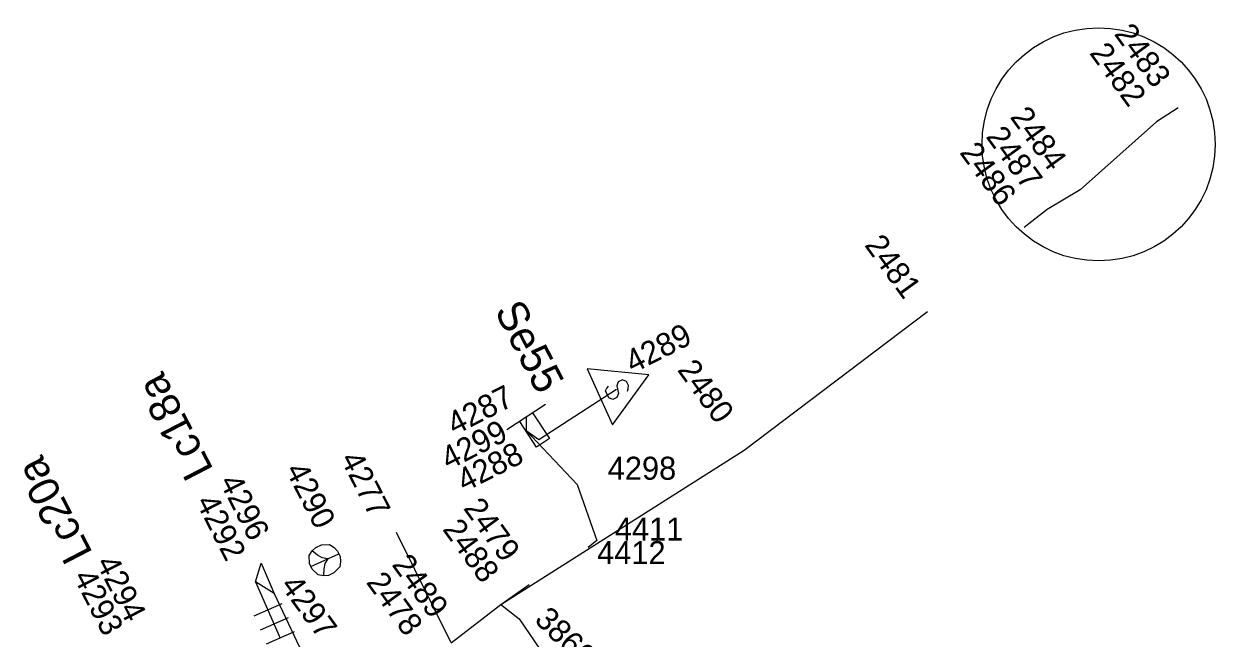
# Model space of a CAD drawing. Extents: x -535557 to -534097, y -1142175 to -1136716.
# Drawn here: x -534895.11 to -534856.28, y -1139139.7 to -1139119.68 of the extents above; entities that cross this region are included whole.
import ezdxf

# ---------------------------------------------------------------- set-up
doc = ezdxf.new("R2010")
doc.units = 0
doc.layers.add('Default', color=7, linetype='Continuous')
doc.layers.add('SS_SZDC', color=7, linetype='Continuous')

# ---------------------------------------------------------------- blocks, each defined once
blk = doc.blocks.new('POINT_DISPLAY')
at = {"layer": 'Default'}
blk.add_line((0, 0), (0, 0), dxfattribs=at)

msp = doc.modelspace()

# ---------------------------------------------------------------- linework, layer by layer
at = {"layer": 'SS_SZDC'}
for p, q in [((-534857.489, -1139122.42), (-534858.189, -1139122.87)), ((-534858.189, -1139122.87), (-534860.68, -1139125.09)), ((-534860.68, -1139125.09), (-534861.75, -1139125.729)), ((-534861.75, -1139125.729), (-534862.51, -1139126.319)), ((-534871.63, -1139133.579), (-534865.659, -1139129.059)), ((-534876.748, -1139130.925), (-534875.925, -1139132.748)), ((-534874.741, -1139131.116), (-534876.748, -1139130.925)), ((-534875.925, -1139132.748), (-534874.741, -1139131.116)), ((-534878.329, -1139133.229), (-534875.789, -1139131.59)), ((-534876.15, -1139131.642), (-534876.125, -1139131.576)), ((-534876.125, -1139131.576), (-534876.054, -1139131.49)), ((-534875.735, -1139131.345), (-534875.785, -1139131.478)), ((-534875.785, -1139131.478), (-534875.728, -1139131.726)), ((-534875.598, -1139131.284), (-534875.735, -1139131.345)), ((-534875.466, -1139131.334), (-534875.598, -1139131.284)), ((-534875.404, -1139131.47), (-534875.466, -1139131.334)), ((-534875.434, -1139131.648), (-534875.409, -1139131.582)), ((-534875.409, -1139131.582), (-534875.404, -1139131.47)), ((-534876.047, -1139131.87), (-534876.15, -1139131.642)), ((-534875.914, -1139131.92), (-534876.047, -1139131.87)), ((-534875.778, -1139131.859), (-534875.914, -1139131.92)), ((-534875.728, -1139131.726), (-534875.778, -1139131.859)), ((-534878.113, -1139132.088), (-534879.366, -1139132.911)), ((-534878.531, -1139132.362), (-534877.982, -1139133.198)), ((-534878.399, -1139133.473), (-534878.948, -1139132.637)), ((-534878.739, -1139132.5), (-534878.739, -1139132.93)), ((-534878.739, -1139132.93), (-534878.329, -1139133.229)), ((-534878.739, -1139132.93), (-534877.079, -1139134.69)), ((-534877.982, -1139133.198), (-534878.399, -1139133.473)), ((-534879.569, -1139138.61), (-534871.63, -1139133.579)), ((-534877.079, -1139134.69), (-534876.439, -1139136.52)), ((-534881.18, -1139139.86), (-534882.97, -1139136.26)), ((-534885.596, -1139136.745), (-534885.414, -1139136.663)), ((-534885.414, -1139136.663), (-534885.145, -1139136.651)), ((-534885.145, -1139136.651), (-534884.992, -1139136.746)), ((-534876.439, -1139136.52), (-534876.72, -1139136.75)), ((-534885.808, -1139137.005), (-534885.713, -1139136.852)), ((-534885.796, -1139137.274), (-534885.808, -1139137.005)), ((-534885.755, -1139137.365), (-534884.844, -1139136.954)), ((-534885.713, -1139136.852), (-534885.596, -1139136.745)), ((-534885.539, -1139136.993), (-534885.713, -1139136.852)), ((-534885.386, -1139137.089), (-534885.539, -1139136.993)), ((-534884.992, -1139136.746), (-534884.885, -1139136.863)), ((-534884.885, -1139136.863), (-534884.803, -1139137.045)), ((-534884.803, -1139137.045), (-534884.786, -1139137.202)), ((-534887.56, -1139137.87), (-534887.38, -1139137.26)), ((-534887.38, -1139137.26), (-534886.949, -1139138.25)), ((-534885.714, -1139137.456), (-534885.796, -1139137.274)), ((-534885.208, -1139137.118), (-534885.386, -1139137.089)), ((-534885.304, -1139137.271), (-534885.333, -1139137.449)), ((-534885.208, -1139137.118), (-534885.304, -1139137.271)), ((-534884.816, -1139137.38), (-534885.003, -1139137.574)), ((-534884.786, -1139137.202), (-534884.816, -1139137.38)), ((-534885.52, -1139137.643), (-534885.714, -1139137.456)), ((-534885.342, -1139137.673), (-534885.52, -1139137.643)), ((-534885.333, -1139137.449), (-534885.342, -1139137.673)), ((-534885.185, -1139137.656), (-534885.342, -1139137.673)), ((-534885.003, -1139137.574), (-534885.185, -1139137.656)), ((-534886.949, -1139138.25), (-534887.56, -1139137.87)), ((-534887.56, -1139137.87), (-534886.753, -1139139.7)), ((-534879.569, -1139138.61), (-534878.64, -1139137.95)), ((-534886.699, -1139138.583), (-534887.614, -1139138.986)), ((-534886.949, -1139138.25), (-534885.25, -1139141.85)), ((-534881.18, -1139139.86), (-534879.569, -1139138.61)), ((-534879.569, -1139138.61), (-534878.97, -1139139.069)), ((-534886.497, -1139139.041), (-534887.412, -1139139.444)), ((-534878.97, -1139139.069), (-534874.71, -1139145.309)), ((-534886.296, -1139139.498), (-534887.211, -1139139.901))]:
    msp.add_line(p, q, dxfattribs=at)
msp.add_circle((-534860.079, -1139123.608), 3.8, dxfattribs=at)

# ---------------------------------------------------------------- block references
for p in [(-534857.489, -1139122.42), (-534858.189, -1139122.87), (-534860.68, -1139125.09), (-534861.75, -1139125.729), (-534862.51, -1139126.319), (-534865.659, -1139129.059), (-534875.789, -1139131.59), (-534878.739, -1139132.5), (-534878.739, -1139132.93), (-534878.329, -1139133.229), (-534871.63, -1139133.579), (-534877.079, -1139134.69), (-534882.97, -1139136.26), (-534876.439, -1139136.52), (-534876.72, -1139136.75), (-534887.38, -1139137.26), (-534885.3, -1139137.159), (-534887.56, -1139137.87), (-534878.64, -1139137.95), (-534886.949, -1139138.25), (-534879.569, -1139138.61), (-534878.97, -1139139.069)]:
    msp.add_blockref('POINT_DISPLAY', p, dxfattribs=at)

# ---------------------------------------------------------------- texts
for s, height, rotation, p in [('2483', 0.75, 306, (-534859.594, -1139120.013)), ('2482', 0.75, 306, (-534860.398, -1139120.634)), ('2484', 0.75, 306, (-534862.988, -1139122.72)), ('2487', 0.75, 306, (-534863.776, -1139123.357)), ('2486', 0.75, 306, (-534864.631, -1139123.877)), ('2481', 0.75, 306, (-534867.732, -1139126.894)), ('Se55', 1, 297.3757, (-534879.785, -1139129.033)), ('4289', 0.75, 27, (-534875.263, -1139131.088)), ('2480', 0.75, 306, (-534873.834, -1139130.962)), ('Lc18a', 1, 117.3757, (-534888.916, -1139134.212)), ('4287', 0.75, 27, (-534881.071, -1139133.102)), ('4299', 0.75, 27, (-534881.269, -1139134.235)), ('4288', 0.75, 27, (-534880.748, -1139134.955)), ('Lc20a', 1, 117.3757, (-534892.853, -1139136.932)), ('4277', 0.75, 297, (-534884.811, -1139133.854)), ('4290', 0.75, 297, (-534886.601, -1139134.217)), ('4296', 0.75, 297, (-534888.754, -1139134.6)), ('4292', 0.75, 297, (-534889.521, -1139135.261)), ('2479', 0.75, 306, (-534880.807, -1139135.472)), ('2488', 0.75, 306, (-534881.486, -1139136.156)), ('2489', 0.75, 306, (-534883.141, -1139137.309)), ('4294', 0.75, 297, (-534892.775, -1139137.245)), ('4293', 0.75, 297, (-534893.514, -1139137.7)), ('4297', 0.75, 306, (-534886.772, -1139137.989)), ('2478', 0.75, 306, (-534883.976, -1139137.885)), ('3860', 0.75, 315, (-534878.502, -1139139.14))]:
    msp.add_text(s, height=height, rotation=rotation, dxfattribs=at).set_placement(p)
for s, p in [('4298', (-534876.079, -1139134.54)), ('4411', (-534875.847, -1139136.521)), ('4412', (-534876.425, -1139137.291))]:
    msp.add_text(s, height=0.75, dxfattribs=at).set_placement(p)

doc.saveas('drawing.dxf')
